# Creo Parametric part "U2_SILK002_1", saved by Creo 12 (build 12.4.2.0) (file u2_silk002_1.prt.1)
Units: Custom; MM, KILOGRAM, SECS

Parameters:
  PTC_WM_ITERATION = "0"
  PTC_WM_VERSION = "-.0"
  PTC_WM_LIFECYCLE_STATE = "In Work"
  PTC_WM_LIFECYCLE = "MO_CADDocument"
  PTC_WM_CREATED_BY = "Maximilian Roepper (Z0017RMS: MO)"
  PTC_WM_CREATED_ON = "18-Sep-26 11:36:42 AM"
  PTC_WM_MODIFIED_BY = "Maximilian Roepper (Z0017RMS: MO)"
  PTC_WM_MODIFIED_ON = "18-Sep-26 11:36:46 AM"
  PDMLINKNUMBER = "PDM000071455004"
  PTC_WM_NAME = "u2_silk002_1.prt"
  PTC_WM_NUMBER = "PDM000071455004"

Other parameters: WEIGHT, WEIGHT_FACTOR, WEIGHT_ADD, _MASS_TEMP, _DIFF_TEMP, MC_ERRORS, SUPPLIER

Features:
  1. coordinate system
  2. datum plane "PRT_YZ"
  3. datum plane "PRT_XY"
  4. datum plane "PRT_XZ"
  5. coordinate system
  6. datum axis
  7. datum axis
  8. datum axis
  9. coordinate system
  10. imported feature

Other named items: PRT, SIEMENS_MO, DRW_VIEW_ORG, PRT_X, PRT_Y, PRT_Z, CS0, ROUGH_GROB

Layers: 00_STD_CSYS-KSYS, 01_STD_PLANES-EBENEN, 02_STD_AXES-ACHSEN, 03_STD_CSYS-KSYS, 24_IMPORT_FEAT-IMPORT_KE

Surfaces: 12 plane, 10 cylinder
